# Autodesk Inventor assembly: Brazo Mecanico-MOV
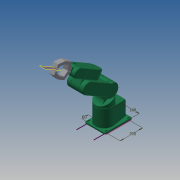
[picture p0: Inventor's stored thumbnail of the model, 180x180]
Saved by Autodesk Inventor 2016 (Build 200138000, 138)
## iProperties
Created: 2012-05
Part Number: Brazo Mecanico-MOV
Document SubType Name: Assembly
Designer: julian.chica
Mass: 1751.25 g
Surface Area: 13800.4 cm^2
Volume: 1751.25 cm^3
Density: 1 g/cm^3
Author: julian.chica
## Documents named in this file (8)
- C:\Test ExamProfessor 2015\Brazo Mecanico-MOV.iam
- C:\Test ExamProfessor 2015\Inventor Básico 2012 - DATASET\06 ENSAMBLE\Robot-Base-Model-A.ipt
- C:\Test ExamProfessor 2015\Inventor Básico 2012 - DATASET\06 ENSAMBLE\Robot-Axis1-2.ipt
- C:\Test ExamProfessor 2015\Inventor Básico 2012 - DATASET\06 ENSAMBLE\Robot-Axis2-3.ipt
- C:\Test ExamProfessor 2015\Inventor Básico 2012 - DATASET\06 ENSAMBLE\Robot-Axis3-4.ipt
- C:\Test ExamProfessor 2015\Inventor Básico 2012 - DATASET\06 ENSAMBLE\Robot-Axis4-5.ipt
- C:\Test ExamProfessor 2015\Inventor Básico 2012 - DATASET\06 ENSAMBLE\Robot-Axis5.ipt
- C:\Test ExamProfessor 2015\Inventor Básico 2012 - DATASET\06 ENSAMBLE\TENAZA.ipt
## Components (7 placed, 7 different names)
1. Robot-Base-Model-A:1 — Insert:1, Angle:1
2. Robot-Axis1-2:1 — Insert:1, Angle:1, Insert:2, Angle:2
3. Robot-Axis2-3:1 — Insert:2, Angle:2, Insert:3, Angle:3
4. Robot-Axis3-4:1 — Insert:3, Angle:3, Insert:4, Angle:4
5. Robot-Axis4-5:1 — Insert:4, Angle:4, Insert:5, Angle:6
6. Robot-Axis5:1 — Insert:5, Mate:1, Mate:2, Angle:5, Angle:6
7. TENAZA:1 — Mate:1, Mate:2, Angle:5
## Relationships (13: Angle 6, Insert 5, Mate 2)
- Insert:1: Robot-Base-Model-A:1 ↔ Robot-Axis1-2:1
- Angle:1: Robot-Base-Model-A:1 ↔ Robot-Axis1-2:1
- Insert:2: Robot-Axis1-2:1 ↔ Robot-Axis2-3:1
- Angle:2: Robot-Axis1-2:1 ↔ Robot-Axis2-3:1
- Insert:3: Robot-Axis2-3:1 ↔ Robot-Axis3-4:1
- Angle:3: Robot-Axis2-3:1 ↔ Robot-Axis3-4:1
- Insert:4: Robot-Axis3-4:1 ↔ Robot-Axis4-5:1
- Angle:4: Robot-Axis3-4:1 ↔ Robot-Axis4-5:1
- Insert:5: Robot-Axis4-5:1 ↔ Robot-Axis5:1
- Mate:1: Robot-Axis5:1 ↔ TENAZA:1
- Mate:2: Robot-Axis5:1 ↔ TENAZA:1
- Angle:5: Robot-Axis5:1 ↔ TENAZA:1
- Angle:6: Robot-Axis4-5:1 ↔ Robot-Axis5:1
